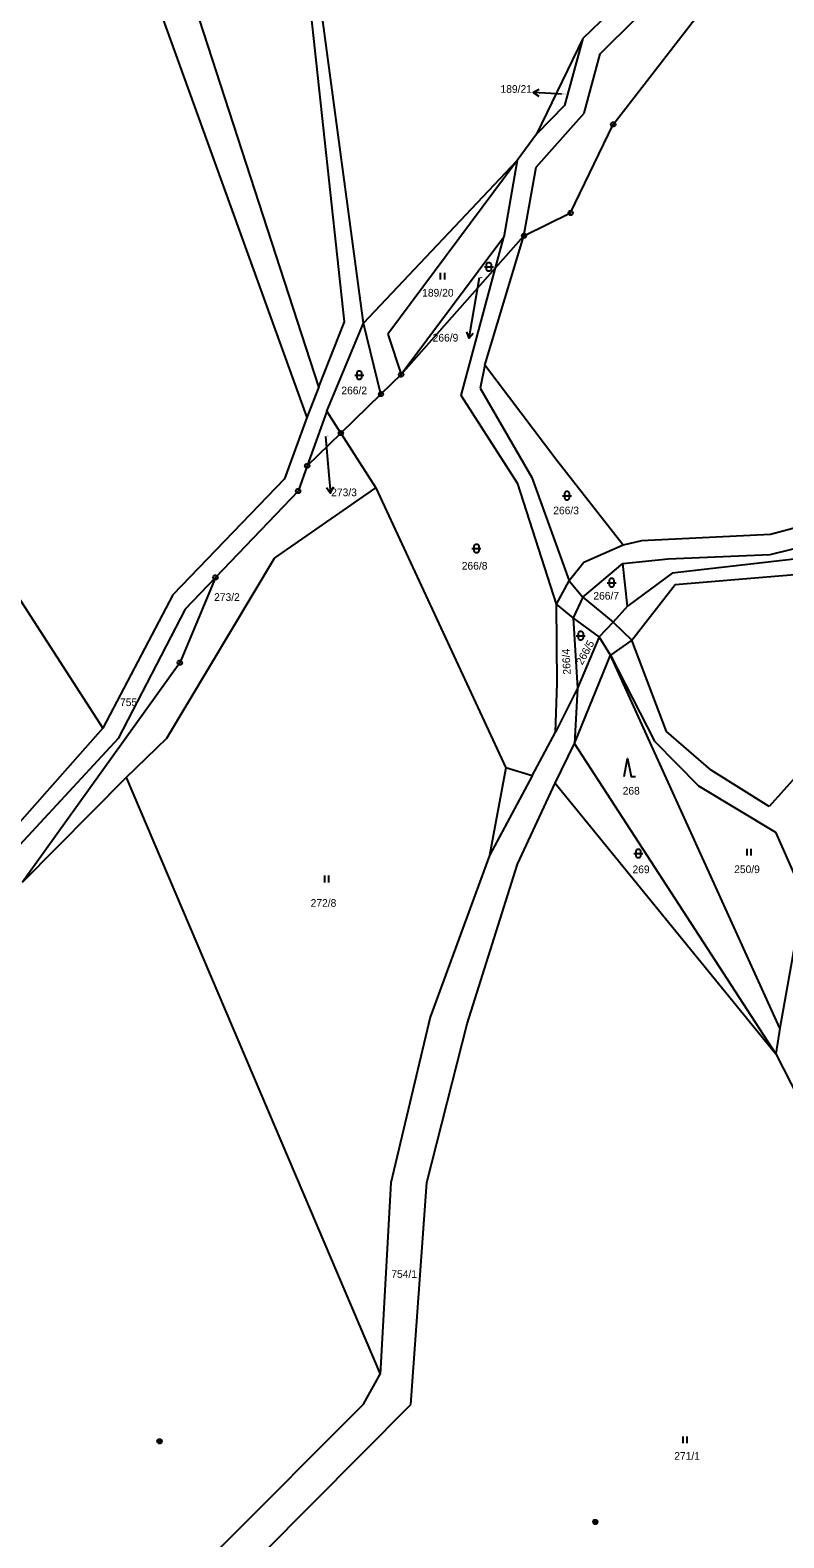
# Model space of a CAD drawing. Extents: x -694465 to -690527, y -983694 to -978978.
# Drawn here: x -693317.7 to -693150.8, y -981137 to -980803.3 of the extents above; entities that cross this region are included whole.
import ezdxf

# ---------------------------------------------------------------- set-up
doc = ezdxf.new("R2010")
doc.units = 0
for name, color, linetype in [('Vrstva 1', 7, 'Continuous'), ('Vrstva 16', 7, 'Continuous'), ('Vrstva 18', 7, 'Continuous'), ('Vrstva 24', 7, 'Continuous'), ('Vrstva 25', 7, 'Continuous'), ('Vrstva 26', 7, 'Continuous'), ('Vrstva 29', 7, 'Continuous')]:
    doc.layers.add(name, color=color, linetype=linetype)

msp = doc.modelspace()

# ---------------------------------------------------------------- linework, layer by layer
at = {"layer": 'Vrstva 1'}
for p, q in [((-693253.774, -980882.199), (-693281.152, -980797.912)), ((-693243.88, -980868.11), (-693209.85, -980832.1)), ((-693253.774, -980882.199), (-693248.11, -980867.81)), ((-693253.774, -980882.199), (-693256.44, -980888.97)), ((-693206.565, -980968.322), (-693201.38, -980958.61)), ((-693206.565, -980968.322), (-693212.39, -980966.53)), ((-693206.565, -980968.322), (-693215.96, -980985.92))]:
    msp.add_line(p, q, dxfattribs=at)
for points in [[(-693191.48, -980808.48), (-693175.63, -980792.74)], [(-693248.11, -980867.81), (-693255.83, -980796.18)], [(-693243.88, -980868.11), (-693253.59, -980796.21)], [(-693289.6, -980797.32), (-693256.44, -980888.97)], [(-693189.49, -980799.48), (-693195.34, -980805.14)], [(-693188.61, -980824.12), (-693170.64, -980800.9)], [(-693195.34, -980805.14), (-693205.6, -980826.25)], [(-693195.34, -980805.14), (-693199.42, -980819.95)], [(-693195.05, -980821.62), (-693191.48, -980808.48)], [(-693199.42, -980819.95), (-693205.6, -980826.25)], [(-693205.64, -980833.6), (-693195.05, -980821.62)], [(-693205.6, -980826.25), (-693209.85, -980832.1)], [(-693198.04, -980843.72), (-693188.61, -980824.12)], [(-693384.5, -980829.37), (-693301.59, -980957.76)], [(-693209.85, -980832.1), (-693238.54, -980870.58)], [(-693209.85, -980832.1), (-693212.84, -980849.08)], [(-693208.36, -980848.75), (-693205.64, -980833.6)], [(-693208.36, -980848.75), (-693198.04, -980843.72)], [(-693212.84, -980849.08), (-693235.56, -980879.5)], [(-693217, -980877.42), (-693208.36, -980848.75)], [(-693214.67, -980855.89), (-693208.36, -980848.75)], [(-693214.67, -980855.89), (-693212.84, -980849.08)], [(-693235.56, -980879.5), (-693214.67, -980855.89)], [(-693222.27, -980884.12), (-693214.67, -980855.89)], [(-693252.02, -980887.6), (-693243.88, -980868.11)], [(-693240.03, -980883.82), (-693243.88, -980868.11)], [(-693238.54, -980870.58), (-693235.56, -980879.5)], [(-693235.56, -980879.5), (-693240.03, -980883.82)], [(-693217, -980877.42), (-693218.08, -980882.5)], [(-693201.11, -980898.52), (-693217, -980877.42)], [(-693218.08, -980882.5), (-693206.61, -980902.28)], [(-693240.03, -980883.82), (-693248.91, -980892.45)], [(-693209.75, -980903.67), (-693222.27, -980884.12)], [(-693256.44, -980888.97), (-693261.37, -980902.58)], [(-693252.02, -980887.6), (-693256.36, -980899.69)], [(-693248.91, -980892.45), (-693252.02, -980887.6)], [(-693256.36, -980899.69), (-693248.91, -980892.45)], [(-693248.91, -980892.45), (-693241.15, -980904.56)], [(-693256.36, -980899.69), (-693258.37, -980905.27)], [(-693186.43, -980917.22), (-693201.11, -980898.52)], [(-693261.37, -980902.58), (-693286.09, -980928.22)], [(-693201.19, -980930.29), (-693209.75, -980903.67)], [(-693206.61, -980902.28), (-693198.39, -980925.13)], [(-693258.37, -980905.27), (-693276.67, -980924.4)], [(-693263.56, -980920.15), (-693241.15, -980904.56)], [(-693241.15, -980904.56), (-693212.39, -980966.53)], [(-693132.03, -980909.07), (-693153.81, -980914.91)], [(-693153.88, -980919.31), (-693130.17, -980913.5)], [(-693182.33, -980916.32), (-693186.43, -980917.22)], [(-693153.81, -980914.91), (-693182.33, -980916.32)], [(-693287.45, -980959.97), (-693263.56, -980920.15)], [(-693186.43, -980917.22), (-693195.13, -980921.1)], [(-693186.49, -980921.3), (-693176.47, -980920.25)], [(-693176.47, -980920.25), (-693153.88, -980919.31)], [(-693130.57, -980918.3), (-693175.55, -980923.47)], [(-693195.13, -980921.1), (-693198.39, -980925.13)], [(-693195.32, -980928.77), (-693186.49, -980921.3)], [(-693185.43, -980930.76), (-693186.49, -980921.3)], [(-693175.55, -980923.47), (-693185.43, -980930.76)], [(-693174.87, -980925.96), (-693129.02, -980922.08)], [(-693276.67, -980924.4), (-693284.57, -980943.26)], [(-693276.67, -980924.4), (-693283.34, -980931.38)], [(-693201.19, -980930.29), (-693198.39, -980925.13)], [(-693198.39, -980925.13), (-693195.32, -980928.77)], [(-693184.5, -980938.3), (-693174.87, -980925.96)], [(-693286.09, -980928.22), (-693301.59, -980957.76)], [(-693197.48, -980933.3), (-693201.19, -980930.29)], [(-693200.98, -980947.89), (-693201.19, -980930.29)], [(-693195.32, -980928.77), (-693197.48, -980933.3)], [(-693195.32, -980928.77), (-693188.6, -980934.31)], [(-693283.34, -980931.38), (-693298.18, -980960.05)], [(-693191.7, -980937.55), (-693197.48, -980933.3)], [(-693197.48, -980933.3), (-693196.51, -980948.92)], [(-693185.43, -980930.76), (-693188.6, -980934.31)], [(-693188.6, -980934.31), (-693191.7, -980937.55)], [(-693188.6, -980934.31), (-693184.5, -980938.3)], [(-693191.7, -980937.55), (-693196.51, -980948.92)], [(-693189.2, -980941.59), (-693191.7, -980937.55)], [(-693184.5, -980938.3), (-693189.2, -980941.59)], [(-693176.8, -980958.5), (-693184.5, -980938.3)], [(-693284.57, -980943.26), (-693319.41, -980991.8)], [(-693197.18, -980961.15), (-693189.2, -980941.59)], [(-693151.7, -981024.17), (-693189.2, -980941.59)], [(-693189.2, -980941.59), (-693179.48, -980960.62)], [(-693201.38, -980958.61), (-693200.98, -980947.89)], [(-693196.51, -980948.92), (-693201.38, -980958.61)], [(-693196.51, -980948.92), (-693197.18, -980961.15)], [(-693132.83, -980951.39), (-693154.08, -980975.114)], [(-693301.59, -980957.76), (-693327.42, -980986.86)], [(-693298.18, -980960.05), (-693325.55, -980989.55)], [(-693296.47, -980968.64), (-693287.45, -980959.97)], [(-693166.93, -980967.05), (-693176.8, -980958.5)], [(-693201.47, -980969.89), (-693197.18, -980961.15)], [(-693152.59, -981029.84), (-693197.18, -980961.15)], [(-693179.48, -980960.62), (-693169.7, -980970.53)], [(-693212.39, -980966.53), (-693215.96, -980985.92)], [(-693154.08, -980975.114), (-693166.93, -980967.05)], [(-693319.41, -980991.8), (-693296.47, -980968.64)], [(-693296.47, -980968.64), (-693240.17, -981100.71)], [(-693209.83, -980987.85), (-693201.47, -980969.89)], [(-693201.47, -980969.89), (-693152.59, -981029.84)], [(-693169.7, -980970.53), (-693152.65, -980980.78)], [(-693152.65, -980980.78), (-693146.45, -980994.8)], [(-693215.96, -980985.92), (-693229.15, -981021.73)], [(-693220.93, -981023.22), (-693209.83, -980987.85)], [(-693146.45, -980994.8), (-693151.7, -981024.17)], [(-693229.15, -981021.73), (-693237.83, -981058.38)], [(-693229.84, -981058.29), (-693220.93, -981023.22)], [(-693151.7, -981024.17), (-693152.59, -981029.84)], [(-693152.59, -981029.84), (-693140.77, -981052.9)], [(-693237.83, -981058.38), (-693240.17, -981100.71)], [(-693233.406, -981107.461), (-693229.84, -981058.29)], [(-693280.193, -981144.086), (-693275.377, -981138.931), (-693243.869, -981107.405), (-693240.17, -981100.71)], [(-693266.21, -981140.43), (-693233.406, -981107.461)]]:
    msp.add_lwpolyline(points, dxfattribs=at)
at = {"layer": 'Vrstva 16'}
for p, q in [((-693200.06, -980817.43), (-693202.33, -980817.3)), ((-693218.3, -980858.11), (-693219.9, -980867.52)), ((-693252.33, -980893.19), (-693251.55, -980901.72))]:
    msp.add_line(p, q, dxfattribs=at)
at = {"layer": 'Vrstva 24'}
for points in [[(-693188.456, -980823.644), (-693188.206, -980823.826), (-693188.11, -980824.12), (-693188.206, -980824.414), (-693188.456, -980824.596), (-693188.764, -980824.596), (-693189.014, -980824.414), (-693189.11, -980824.12), (-693189.014, -980823.826), (-693188.764, -980823.644)], [(-693197.886, -980843.244), (-693197.636, -980843.426), (-693197.54, -980843.72), (-693197.636, -980844.014), (-693197.886, -980844.196), (-693198.194, -980844.196), (-693198.444, -980844.014), (-693198.54, -980843.72), (-693198.444, -980843.426), (-693198.194, -980843.244)], [(-693208.206, -980848.274), (-693207.956, -980848.456), (-693207.86, -980848.75), (-693207.956, -980849.044), (-693208.206, -980849.226), (-693208.514, -980849.226), (-693208.764, -980849.044), (-693208.86, -980848.75), (-693208.764, -980848.456), (-693208.514, -980848.274)], [(-693235.406, -980879.024), (-693235.156, -980879.206), (-693235.06, -980879.5), (-693235.156, -980879.794), (-693235.406, -980879.976), (-693235.714, -980879.976), (-693235.964, -980879.794), (-693236.06, -980879.5), (-693235.964, -980879.206), (-693235.714, -980879.024)], [(-693239.876, -980883.344), (-693239.626, -980883.526), (-693239.53, -980883.82), (-693239.626, -980884.114), (-693239.876, -980884.296), (-693240.184, -980884.296), (-693240.434, -980884.114), (-693240.53, -980883.82), (-693240.434, -980883.526), (-693240.184, -980883.344)], [(-693248.756, -980891.974), (-693248.506, -980892.156), (-693248.41, -980892.45), (-693248.506, -980892.744), (-693248.756, -980892.926), (-693249.064, -980892.926), (-693249.314, -980892.744), (-693249.41, -980892.45), (-693249.314, -980892.156), (-693249.064, -980891.974)], [(-693256.206, -980899.214), (-693255.956, -980899.396), (-693255.86, -980899.69), (-693255.956, -980899.984), (-693256.206, -980900.166), (-693256.514, -980900.166), (-693256.764, -980899.984), (-693256.86, -980899.69), (-693256.764, -980899.396), (-693256.514, -980899.214)], [(-693258.216, -980904.794), (-693257.966, -980904.976), (-693257.87, -980905.27), (-693257.966, -980905.564), (-693258.216, -980905.746), (-693258.524, -980905.746), (-693258.774, -980905.564), (-693258.87, -980905.27), (-693258.774, -980904.976), (-693258.524, -980904.794)], [(-693276.516, -980923.924), (-693276.266, -980924.106), (-693276.17, -980924.4), (-693276.266, -980924.694), (-693276.516, -980924.876), (-693276.824, -980924.876), (-693277.074, -980924.694), (-693277.17, -980924.4), (-693277.074, -980924.106), (-693276.824, -980923.924)], [(-693284.416, -980942.784), (-693284.166, -980942.966), (-693284.07, -980943.26), (-693284.166, -980943.554), (-693284.416, -980943.736), (-693284.724, -980943.736), (-693284.974, -980943.554), (-693285.07, -980943.26), (-693284.974, -980942.966), (-693284.724, -980942.784)]]:
    msp.add_lwpolyline(points, close=True, dxfattribs=at)
for points in [[(-693188.729, -980824.12), (-693188.49, -980824.12)], [(-693198.159, -980843.72), (-693197.92, -980843.72)], [(-693208.479, -980848.75), (-693208.24, -980848.75)], [(-693235.679, -980879.5), (-693235.44, -980879.5)], [(-693240.149, -980883.82), (-693239.91, -980883.82)], [(-693249.029, -980892.45), (-693248.79, -980892.45)], [(-693256.479, -980899.69), (-693256.24, -980899.69)], [(-693258.489, -980905.27), (-693258.25, -980905.27)], [(-693276.789, -980924.4), (-693276.55, -980924.4)], [(-693284.689, -980943.26), (-693284.45, -980943.26)]]:
    msp.add_lwpolyline(points, dxfattribs=at)
at = {"layer": 'Vrstva 25'}
for points in [[(-693226.92, -980856.96), (-693226.92, -980858.46)], [(-693225.92, -980858.46), (-693225.92, -980856.96)], [(-693217.14, -980855.64), (-693215.14, -980855.64)], [(-693245.83, -980879.64), (-693243.83, -980879.64)], [(-693199.84, -980906.3), (-693197.84, -980906.3)], [(-693219.88, -980917.98), (-693217.88, -980917.98)], [(-693189.96, -980925.55), (-693187.96, -980925.55)], [(-693196.78, -980937.29), (-693194.78, -980937.29)], [(-693186.16, -980968.47), (-693185.41, -980964.47), (-693184.66, -980968.47), (-693183.66, -980968.47)], [(-693184.05, -980985.5), (-693182.05, -980985.5)], [(-693159.06, -980984.43), (-693159.06, -980985.93)], [(-693158.06, -980985.93), (-693158.06, -980984.43)], [(-693252.54, -980990.39), (-693252.54, -980991.89)], [(-693251.54, -980991.89), (-693251.54, -980990.39)], [(-693173.22, -981114.53), (-693173.22, -981116.03)], [(-693172.22, -981116.03), (-693172.22, -981114.53)]]:
    msp.add_lwpolyline(points, dxfattribs=at)
for points in [[(-693216.64, -980855.14), (-693216.545, -980854.846), (-693216.295, -980854.664), (-693215.985, -980854.664), (-693215.735, -980854.846), (-693215.64, -980855.14), (-693215.64, -980856.14), (-693215.735, -980856.434), (-693215.985, -980856.616), (-693216.295, -980856.616), (-693216.545, -980856.434), (-693216.64, -980856.14)], [(-693245.33, -980879.14), (-693245.235, -980878.846), (-693244.985, -980878.664), (-693244.675, -980878.664), (-693244.425, -980878.846), (-693244.33, -980879.14), (-693244.33, -980880.14), (-693244.425, -980880.434), (-693244.675, -980880.616), (-693244.985, -980880.616), (-693245.235, -980880.434), (-693245.33, -980880.14)], [(-693199.34, -980905.8), (-693199.245, -980905.506), (-693198.995, -980905.324), (-693198.685, -980905.324), (-693198.435, -980905.506), (-693198.34, -980905.8), (-693198.34, -980906.8), (-693198.435, -980907.094), (-693198.685, -980907.276), (-693198.995, -980907.276), (-693199.245, -980907.094), (-693199.34, -980906.8)], [(-693219.38, -980917.48), (-693219.285, -980917.186), (-693219.035, -980917.004), (-693218.725, -980917.004), (-693218.475, -980917.186), (-693218.38, -980917.48), (-693218.38, -980918.48), (-693218.475, -980918.774), (-693218.725, -980918.956), (-693219.035, -980918.956), (-693219.285, -980918.774), (-693219.38, -980918.48)], [(-693189.46, -980925.05), (-693189.365, -980924.756), (-693189.115, -980924.574), (-693188.805, -980924.574), (-693188.555, -980924.756), (-693188.46, -980925.05), (-693188.46, -980926.05), (-693188.555, -980926.344), (-693188.805, -980926.526), (-693189.115, -980926.526), (-693189.365, -980926.344), (-693189.46, -980926.05)], [(-693196.28, -980936.79), (-693196.185, -980936.496), (-693195.935, -980936.314), (-693195.625, -980936.314), (-693195.375, -980936.496), (-693195.28, -980936.79), (-693195.28, -980937.79), (-693195.375, -980938.084), (-693195.625, -980938.266), (-693195.935, -980938.266), (-693196.185, -980938.084), (-693196.28, -980937.79)], [(-693183.55, -980985), (-693183.455, -980984.706), (-693183.205, -980984.524), (-693182.895, -980984.524), (-693182.645, -980984.706), (-693182.55, -980985), (-693182.55, -980986), (-693182.645, -980986.294), (-693182.895, -980986.476), (-693183.205, -980986.476), (-693183.455, -980986.294), (-693183.55, -980986)]]:
    msp.add_lwpolyline(points, close=True, dxfattribs=at)
at = {"layer": 'Vrstva 26'}
for points in [[(-693289.195, -981115.094), (-693288.885, -981115.094), (-693288.635, -981115.276), (-693288.54, -981115.57), (-693288.635, -981115.864), (-693288.885, -981116.046), (-693289.195, -981116.046), (-693289.445, -981115.864), (-693289.54, -981115.57), (-693289.445, -981115.276), (-693289.195, -981115.094), (-693289.16, -981115.13), (-693288.92, -981115.13), (-693288.76, -981115.21), (-693289.32, -981115.21), (-693289.4, -981115.29), (-693288.68, -981115.29), (-693288.68, -981115.37), (-693289.4, -981115.37), (-693289.442, -981115.45), (-693288.64, -981115.451), (-693288.6, -981115.53), (-693289.48, -981115.53), (-693289.48, -981115.61), (-693288.6, -981115.61), (-693288.631, -981115.689), (-693289.445, -981115.689), (-693289.439, -981115.77), (-693288.631, -981115.77), (-693288.68, -981115.85), (-693289.4, -981115.85), (-693289.32, -981115.93), (-693288.76, -981115.93), (-693288.868, -981116.009), (-693289.208, -981116.009)], [(-693192.735, -981132.954), (-693192.425, -981132.954), (-693192.175, -981133.136), (-693192.08, -981133.43), (-693192.175, -981133.724), (-693192.425, -981133.906), (-693192.735, -981133.906), (-693192.985, -981133.724), (-693193.08, -981133.43), (-693192.985, -981133.136), (-693192.735, -981132.954), (-693192.7, -981132.99), (-693192.46, -981132.99), (-693192.3, -981133.07), (-693192.86, -981133.07), (-693192.94, -981133.15), (-693192.22, -981133.15), (-693192.22, -981133.23), (-693192.94, -981133.23), (-693192.982, -981133.31), (-693192.18, -981133.311), (-693192.14, -981133.39), (-693193.02, -981133.39), (-693193.02, -981133.47), (-693192.14, -981133.47), (-693192.171, -981133.549), (-693192.985, -981133.549), (-693192.979, -981133.63), (-693192.171, -981133.63), (-693192.22, -981133.71), (-693192.94, -981133.71), (-693192.86, -981133.79), (-693192.3, -981133.79), (-693192.408, -981133.869), (-693192.748, -981133.869)], [(-693192.735, -981132.954), (-693192.425, -981132.954), (-693192.175, -981133.136), (-693192.08, -981133.43), (-693192.175, -981133.724), (-693192.425, -981133.906), (-693192.735, -981133.906), (-693192.985, -981133.724), (-693193.08, -981133.43), (-693192.985, -981133.136), (-693192.735, -981132.954), (-693192.7, -981132.99), (-693192.46, -981132.99), (-693192.3, -981133.07), (-693192.86, -981133.07), (-693192.94, -981133.15), (-693192.22, -981133.15), (-693192.22, -981133.23), (-693192.94, -981133.23), (-693192.982, -981133.31), (-693192.18, -981133.311), (-693192.14, -981133.39), (-693193.02, -981133.39), (-693193.02, -981133.47), (-693192.14, -981133.47), (-693192.171, -981133.549), (-693192.985, -981133.549), (-693192.979, -981133.63), (-693192.171, -981133.63), (-693192.22, -981133.71), (-693192.94, -981133.71), (-693192.86, -981133.79), (-693192.3, -981133.79), (-693192.408, -981133.869), (-693192.748, -981133.869)]]:
    msp.add_lwpolyline(points, dxfattribs=at)
at = {"layer": 'Vrstva 29'}
for points in [[(-693204.983, -980816.398), (-693206.324, -980817.073)], [(-693202.33, -980817.3), (-693206.324, -980817.073), (-693205.068, -980817.896)], [(-693221.092, -980870.056), (-693220.571, -980871.463)], [(-693219.9, -980867.52), (-693220.571, -980871.463), (-693219.614, -980870.308)], [(-693251.55, -980901.72), (-693251.189, -980905.704), (-693250.559, -980904.341)], [(-693252.053, -980904.477), (-693251.189, -980905.704)]]:
    msp.add_lwpolyline(points, dxfattribs=at)

# ---------------------------------------------------------------- texts
at = {"layer": 'Vrstva 16'}
for s, p in [('189/21', (-693213.562, -980817.13)), ('266/9', (-693228.587, -980872.18)), ('273/3', (-693251.043, -980906.41))]:
    msp.add_text(s, height=1.7, dxfattribs=at).set_placement(p)
at = {"layer": 'Vrstva 18'}
for s, height, p in [('189/21', 0.2, (-693200.014, -980817.43)), ('266/9', 0.2, (-693218.272, -980858.11)), ('189/20', 1.7, (-693230.902, -980862.23)), ('266/2', 1.7, (-693248.79, -980883.86)), ('273/3', 0.2, (-693252.302, -980893.19)), ('266/3', 1.7, (-693201.884, -980910.41)), ('266/8', 1.7, (-693222.133, -980922.66)), ('273/2', 1.7, (-693276.963, -980929.58)), ('266/7', 1.7, (-693193.007, -980929.3)), ('755', 1.7, (-693297.788, -980952.86)), ('268', 1.7, (-693186.518, -980972.45)), ('269', 1.7, (-693184.338, -980989.85)), ('250/9', 1.7, (-693161.83, -980989.83)), ('272/8', 1.7, (-693255.6, -980997.29)), ('754/1', 1.7, (-693237.732, -981079.42)), ('271/1', 1.7, (-693175.093, -981119.68))]:
    msp.add_text(s, height=height, dxfattribs=at).set_placement(p)
for s, rotation, p in [('266/4', 92.70457, (-693197.995, -980945.853)), ('266/5', 61.19189, (-693195.452, -980943.894))]:
    msp.add_text(s, height=1.7, rotation=rotation, dxfattribs=at).set_placement(p)

doc.saveas('drawing.dxf')
